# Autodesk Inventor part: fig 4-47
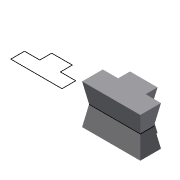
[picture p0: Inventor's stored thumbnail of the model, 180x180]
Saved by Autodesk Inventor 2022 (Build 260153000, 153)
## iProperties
Created: 2004-05
Part Number: fig 4-47
Document SubType Name: Modeling
Designer: CADCIM Technologies
Manufacturer: Standard
Standards Organization: Custom
Density: 1 g/cm^3
Material: Generic
Appearance: Default
Author: CADCIM Technologies
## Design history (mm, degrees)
sketch "Sketch1"
  geometry: L1 (31.783, 34.561)-(31.783, 22.933); L2 (31.783, 22.933)-(16.796, 22.933); L3 (16.796, 22.933)-(16.796, 9.496); L4 (16.796, 9.496)-(66.925, 9.496); L5 (66.925, 9.496)-(66.925, 22.933); L6 (66.925, 22.933)-(51.938, 22.933); L7 (51.938, 22.933)-(51.938, 34.561); L8 (51.938, 34.561)-(31.783, 34.561); L9 (-45.013, 34.561)-(-45.013, 22.933); L10 (-45.013, 22.933)-(-60, 22.933); L11 (-60, 22.933)-(-60, 9.496); L12 (-60, 9.496)-(-9.871, 9.496); L13 (-9.871, 9.496)-(-9.871, 22.933); L14 (-9.871, 22.933)-(-24.858, 22.933); L15 (-24.858, 22.933)-(-24.858, 34.561); L16 (-24.858, 34.561)-(-45.013, 34.561)
  constraints: 32 end point, 10 parallel, 4 equal length, 2 collinear, 2 perpendicular, 2 vertical
extrude "Extrusion2" new body sketch "Sketch1" stored distance "d2" = 38.75; taper "d3" = 10 deg
body "Solid2"
